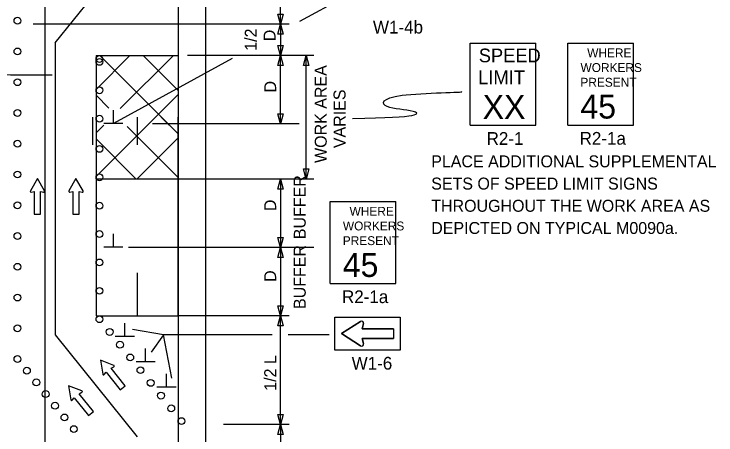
# Model space of a CAD drawing. Extents: x 16525 to 18479, y 5726 to 6926.
# Drawn here: x 16973 to 17383.9, y 6323.4 to 6569.7 of the extents above; entities that cross this region are included whole.
import ezdxf

# ---------------------------------------------------------------- set-up
doc = ezdxf.new("R2010")
doc.units = 0
for name, color, linetype in [('ALI_LEGAL_EX', 7, 'Continuous'), ('MT_SCRATCH_LEVEL_A', 7, 'Continuous'), ('MT_SCRATCH_LEVEL_E', 7, 'Continuous'), ('PAVT_EDGE_EX', 7, 'Continuous'), ('TRAFFIC_SIGNS_PR', 7, 'Continuous'), ('TYPICAL_TEXT_DIMEN_PR', 7, 'Continuous')]:
    doc.layers.add(name, color=color, linetype=linetype)

msp = doc.modelspace()

# ---------------------------------------------------------------- linework, layer by layer
at = {"layer": 'ALI_LEGAL_EX'}
for points in [[(17019, 6509.42), (17019, 6493.24)], [(17019, 6509.42), (17019, 6493.24)], [(17045, 6509.42), (17045, 6493.24)], [(17045, 6509.42), (17045, 6493.24)], [(17045, 6418.24), (17045, 6393.24)]]:
    msp.add_lwpolyline(points, dxfattribs=at)
at = {"layer": 'MT_SCRATCH_LEVEL_A'}
for p, q in [((17021, 6545.42), (17069, 6545.42)), ((17021, 6525.61), (17040.8, 6545.42)), ((17069, 6499.61), (17023.19, 6545.42)), ((17035.2, 6514.35), (17066.26, 6545.42)), ((17069, 6525.07), (17048.65, 6545.42)), ((17021, 6474.7), (17069, 6522.7)), ((17028.49, 6514.66), (17021, 6522.16)), ((17069, 6499.61), (17059.19, 6509.42)), ((17069, 6509.42), (17069, 6393.18)), ((17069, 6425.24), (17069, 6509.42)), ((17069, 6509.42), (17069, 6393.18)), ((17069, 6425.24), (17069, 6509.42)), ((17021, 6500.15), (17025.63, 6504.78)), ((17021, 6500.15), (17025.63, 6504.78)), ((17069, 6474.16), (17039.24, 6503.91)), ((17069, 6474.16), (17039.38, 6503.77)), ((17044.55, 6473.15), (17021, 6496.7)), ((17044.9, 6473.15), (17069, 6497.24))]:
    msp.add_line(p, q, dxfattribs=at)
at = {"layer": 'MT_SCRATCH_LEVEL_E'}
for p, q in [((16986.68, 6473.41), (16982.57, 6466.17)), ((16986.68, 6473.41), (16982.57, 6466.17)), ((16986.68, 6473.41), (16982.57, 6466.17)), ((16986.68, 6473.41), (16982.57, 6466.17)), ((16990.83, 6466.17), (16986.68, 6473.41)), ((16990.83, 6466.17), (16986.68, 6473.41)), ((16990.83, 6466.17), (16986.68, 6473.41)), ((16990.83, 6466.17), (16986.68, 6473.41)), ((17009.26, 6473.41), (17005.15, 6466.17)), ((17009.26, 6473.41), (17005.15, 6466.17)), ((17013.41, 6466.17), (17009.26, 6473.41)), ((17013.41, 6466.17), (17009.26, 6473.41)), ((16983.05, 6465.48), (16984.83, 6465.8)), ((16983.05, 6465.48), (16984.83, 6465.8)), ((16983.05, 6465.48), (16984.83, 6465.8)), ((16983.05, 6465.48), (16984.83, 6465.8)), ((16984.83, 6465.8), (16984.83, 6452.54)), ((16984.83, 6465.8), (16984.83, 6452.54)), ((16984.83, 6465.8), (16984.83, 6452.54)), ((16984.83, 6465.8), (16984.83, 6452.54)), ((16988.57, 6452.54), (16988.57, 6465.8)), ((16988.57, 6465.8), (16990.35, 6465.48)), ((16988.57, 6452.54), (16988.57, 6465.8)), ((16988.57, 6465.8), (16990.35, 6465.48)), ((16988.57, 6452.54), (16988.57, 6465.8)), ((16988.57, 6465.8), (16990.35, 6465.48)), ((16988.57, 6452.54), (16988.57, 6465.8)), ((16988.57, 6465.8), (16990.35, 6465.48)), ((17005.63, 6465.48), (17007.41, 6465.8)), ((17005.63, 6465.48), (17007.41, 6465.8)), ((17007.41, 6465.8), (17007.41, 6452.54)), ((17007.41, 6465.8), (17007.41, 6452.54)), ((17011.15, 6452.54), (17011.15, 6465.8)), ((17011.15, 6465.8), (17012.93, 6465.48)), ((17011.15, 6452.54), (17011.15, 6465.8)), ((17011.15, 6465.8), (17012.93, 6465.48)), ((16984.83, 6452.54), (16988.57, 6452.54)), ((16984.83, 6452.54), (16988.57, 6452.54)), ((16984.83, 6452.54), (16988.57, 6452.54)), ((16984.83, 6452.54), (16988.57, 6452.54)), ((17007.41, 6452.54), (17011.15, 6452.54)), ((17007.41, 6452.54), (17011.15, 6452.54)), ((17023.57, 6367.17), (17024.91, 6358.95)), ((17031.34, 6364.13), (17023.57, 6367.17)), ((17023.57, 6367.17), (17024.91, 6358.95)), ((17031.34, 6364.13), (17023.57, 6367.17)), ((17025.71, 6358.72), (17026.9, 6360.08)), ((17025.71, 6358.72), (17026.9, 6360.08)), ((17026.9, 6360.08), (17035.21, 6349.76)), ((17026.9, 6360.08), (17035.21, 6349.76)), ((17029.81, 6362.43), (17031.4, 6363.3)), ((17029.81, 6362.43), (17031.4, 6363.3)), ((17038.13, 6352.1), (17029.81, 6362.43)), ((17038.13, 6352.1), (17029.81, 6362.43)), ((17004.93, 6352.25), (17006.27, 6344.03)), ((17012.7, 6349.21), (17004.93, 6352.25)), ((17004.93, 6352.25), (17006.27, 6344.03)), ((17012.7, 6349.21), (17004.93, 6352.25)), ((17035.21, 6349.76), (17038.13, 6352.1)), ((17035.21, 6349.76), (17038.13, 6352.1)), ((17011.17, 6347.51), (17012.76, 6348.38)), ((17011.17, 6347.51), (17012.76, 6348.38)), ((17007.07, 6343.8), (17008.26, 6345.16)), ((17007.07, 6343.8), (17008.26, 6345.16)), ((17008.26, 6345.16), (17016.58, 6334.83)), ((17008.26, 6345.16), (17016.58, 6334.83)), ((17019.49, 6337.18), (17011.17, 6347.51)), ((17019.49, 6337.18), (17011.17, 6347.51)), ((17016.58, 6334.83), (17019.49, 6337.18)), ((17016.58, 6334.83), (17019.49, 6337.18))]:
    msp.add_line(p, q, dxfattribs=at)
for centre, start, end in [((16982.98, 6465.94), 150.4248, 279.9638), ((16982.98, 6465.94), 150.4248, 279.9638), ((16982.98, 6465.94), 150.4248, 279.9638), ((16982.98, 6465.94), 150.4248, 279.9638), ((16990.42, 6465.94), 260.0362, 29.7731), ((16990.42, 6465.94), 260.0362, 29.7731), ((16990.42, 6465.94), 260.0362, 29.7731), ((16990.42, 6465.94), 260.0362, 29.7731), ((17005.56, 6465.94), 150.4248, 279.9638), ((17005.56, 6465.94), 150.4248, 279.9638), ((17013, 6465.94), 260.0362, 29.7731), ((17013, 6465.94), 260.0362, 29.7731), ((17031.16, 6363.7), 298.877, 68.6139), ((17031.16, 6363.7), 298.877, 68.6139), ((17025.37, 6359.03), 189.2656, 318.8046), ((17025.37, 6359.03), 189.2656, 318.8046), ((17012.52, 6348.78), 298.877, 68.6139), ((17012.52, 6348.78), 298.877, 68.6139), ((17006.73, 6344.11), 189.2656, 318.8046), ((17006.73, 6344.11), 189.2656, 318.8046)]:
    msp.add_arc(centre, 0.463, start, end, dxfattribs=at)
at = {"layer": 'PAVT_EDGE_EX'}
for p, q in [((17069, 6926.09), (17069, 6062.8)), ((17085, 6926.09), (17085, 6062.8)), ((16991.07, 6912.1), (16991.07, 6082.91)), ((16997, 6552.78), (17045, 6612.39)), ((16997, 6552.78), (16997, 6381.96)), ((17021, 6545.42), (17021, 6393.18)), ((16997, 6381.96), (17045, 6322.35))]:
    msp.add_line(p, q, dxfattribs=at)
msp.add_lwpolyline([(17069, 6473.15), (17021.04, 6473.15), (17021.04, 6393.18), (17069, 6393.18)], close=True, dxfattribs=at)
at = {"layer": 'TRAFFIC_SIGNS_PR'}
for p, q in [((17239.99, 6552.62), (17278.39, 6552.62)), ((17239.99, 6504.62), (17239.99, 6552.62)), ((17278.39, 6504.62), (17278.39, 6552.62)), ((17297.18, 6552.71), (17335.58, 6552.71)), ((17297.18, 6504.71), (17297.18, 6552.71)), ((17335.58, 6504.71), (17335.58, 6552.71)), ((17239.99, 6504.62), (17278.39, 6504.62)), ((17297.18, 6504.71), (17335.58, 6504.71)), ((17158.1, 6460.01), (17196.5, 6460.01)), ((17158.1, 6412.01), (17158.1, 6460.01)), ((17196.5, 6412.01), (17196.5, 6460.01)), ((17158.1, 6412.01), (17196.5, 6412.01)), ((17175.84, 6389.81), (17164.68, 6382.7)), ((17176.69, 6385.5), (17177.52, 6388.56)), ((17195.08, 6385.5), (17176.69, 6385.5)), ((17195.08, 6385.5), (17195.08, 6379.9)), ((17164.68, 6382.7), (17175.84, 6375.6)), ((17177.52, 6376.84), (17176.69, 6379.9)), ((17176.69, 6379.9), (17195.08, 6379.9))]:
    msp.add_line(p, q, dxfattribs=at)
msp.add_lwpolyline([(17199.08, 6373.1), (17160.68, 6373.1), (17160.68, 6392.3), (17199.08, 6392.3)], close=True, dxfattribs=at)
for points in [[(17175.84, 6375.6), (17164.68, 6382.7), (17175.84, 6389.81)], [(17177.52, 6388.56), (17176.69, 6385.5), (17195.08, 6385.5), (17195.08, 6379.9), (17176.69, 6379.9), (17177.52, 6376.84)]]:
    msp.add_lwpolyline(points, dxfattribs=at)
for centre in [(16975, 6565.82), (16975, 6547.82), (17023, 6543.41), (17023, 6541.72), (16975, 6529.82), (17023, 6525.1), (16975, 6511.82), (17023, 6508.49), (16975, 6493.82), (17023, 6490.8), (16975, 6475.82), (17023, 6474.19), (16975, 6457.82), (17023, 6457.58), (17023, 6440.97), (16975, 6439.82), (17023, 6424.36), (16975, 6421.82), (17023, 6407.74), (16975, 6403.82), (17023, 6391.13), (16975, 6385.82), (17029, 6383.68), (17035, 6376.23), (16975, 6367.82), (17041, 6368.78), (16980.5, 6360.99), (17047, 6361.32), (16986, 6354.16), (17053, 6353.87), (16991.5, 6347.33), (17059, 6346.42), (16997, 6340.5), (17065, 6338.97), (17002.5, 6333.67), (17071, 6331.52), (17008, 6326.84)]:
    msp.add_circle(centre, 2, dxfattribs=at)
for centre, start, end in [((17176.44, 6388.86), 344.6731, 122.4696), ((17176.44, 6388.86), 344.6731, 122.4696), ((17176.44, 6376.55), 237.5304, 15.3269), ((17176.44, 6376.55), 237.5304, 15.3269)]:
    msp.add_arc(centre, 1.12, start, end, dxfattribs=at)
at = {"layer": 'TYPICAL_TEXT_DIMEN_PR'}
for p, q in [((17129, 6563.82), (17129, 6622.47)), ((17176.23, 6585.1), (17140.02, 6565.3)), ((17129, 6563.82), (17127.43, 6569.69)), ((17127.43, 6569.69), (17129, 6569.69)), ((17129, 6569.69), (17130.57, 6569.69)), ((17130.57, 6569.69), (17129, 6563.82)), ((17134, 6563.82), (16984.16, 6563.82)), ((17127.43, 6557.96), (17129, 6563.82)), ((17129, 6563.82), (17130.57, 6557.96)), ((17129, 6563.82), (17129, 6545.42)), ((17129, 6557.96), (17127.43, 6557.96)), ((17130.57, 6557.96), (17129, 6557.96)), ((17129, 6545.42), (17127.43, 6551.28)), ((17127.43, 6551.28), (17129, 6551.28)), ((17129, 6551.28), (17130.57, 6551.28)), ((17130.57, 6551.28), (17129, 6545.42)), ((17148.57, 6545.42), (17074.5, 6545.42)), ((17127.43, 6539.55), (17129, 6545.42)), ((17129, 6505.42), (17129, 6545.42)), ((17129, 6545.42), (17130.57, 6539.55)), ((17142.43, 6539.55), (17144, 6545.42)), ((17144, 6473.18), (17144, 6545.42)), ((17144, 6545.42), (17145.57, 6539.55)), ((17100.59, 6543.74), (17031.13, 6505.76)), ((17129, 6539.55), (17127.43, 6539.55)), ((17130.57, 6539.55), (17129, 6539.55)), ((17144, 6539.55), (17142.43, 6539.55)), ((17145.57, 6539.55), (17144, 6539.55)), ((17031.13, 6505.76), (17031.13, 6513.54)), ((17129, 6505.42), (17127.43, 6511.28)), ((17127.43, 6511.28), (17129, 6511.28)), ((17129, 6511.28), (17130.57, 6511.28)), ((17130.57, 6511.28), (17129, 6505.42)), ((17036.75, 6505.76), (17025.5, 6505.76)), ((17139.87, 6505.42), (17054.06, 6505.42)), ((17144, 6473.18), (17142.43, 6479.05)), ((17142.43, 6479.05), (17144, 6479.05)), ((17144, 6479.05), (17145.57, 6479.05)), ((17145.57, 6479.05), (17144, 6473.18)), ((17148.57, 6473.18), (17069, 6473.18)), ((17127.43, 6467.32), (17129, 6473.18)), ((17129, 6473.18), (17129, 6433.18)), ((17129, 6473.18), (17130.57, 6467.32)), ((17129, 6467.32), (17127.43, 6467.32)), ((17130.57, 6467.32), (17129, 6467.32)), ((17031.13, 6433.33), (17031.13, 6441.12)), ((17129, 6433.18), (17127.43, 6439.05)), ((17127.43, 6439.05), (17129, 6439.05)), ((17129, 6439.05), (17130.57, 6439.05)), ((17130.57, 6439.05), (17129, 6433.18)), ((17036.75, 6433.33), (17025.5, 6433.33)), ((17148.57, 6433.18), (17039.94, 6433.18)), ((17127.43, 6427.32), (17129, 6433.18)), ((17129, 6433.18), (17129, 6393.18)), ((17129, 6433.18), (17130.57, 6427.32)), ((17129, 6427.32), (17127.43, 6427.32)), ((17130.57, 6427.32), (17129, 6427.32)), ((17129, 6393.18), (17127.43, 6399.05)), ((17127.43, 6399.05), (17129, 6399.05)), ((17129, 6399.05), (17130.57, 6399.05)), ((17130.57, 6399.05), (17129, 6393.18)), ((17134, 6393.18), (17069, 6393.18)), ((17127.43, 6387.32), (17129, 6393.18)), ((17129, 6393.18), (17130.57, 6387.32)), ((17129, 6329.52), (17129, 6393.18)), ((17037.82, 6381.1), (17037.82, 6388.88)), ((17060.4, 6381.92), (17042.4, 6385.18)), ((17129, 6387.32), (17127.43, 6387.32)), ((17130.57, 6387.32), (17129, 6387.32)), ((17043.44, 6381.1), (17032.19, 6381.1)), ((17060.4, 6381.92), (17053.25, 6371.85)), ((17065.45, 6356.62), (17060.4, 6381.92)), ((17124.02, 6381.92), (17060.4, 6381.92)), ((17157.37, 6381.92), (17133.51, 6381.92)), ((17050.04, 6366.24), (17050.04, 6374.02)), ((17055.67, 6366.24), (17044.42, 6366.24)), ((17062.27, 6351.38), (17062.27, 6359.16)), ((17067.89, 6351.38), (17056.64, 6351.38)), ((17129, 6329.52), (17127.43, 6335.38)), ((17127.43, 6335.38), (17129, 6335.38)), ((17129, 6335.38), (17130.57, 6335.38)), ((17130.57, 6335.38), (17129, 6329.52)), ((17134, 6329.52), (17095.62, 6329.52)), ((17127.43, 6323.65), (17129, 6329.52)), ((17129, 6329.52), (17129, 6289.52)), ((17129, 6329.52), (17130.57, 6323.65)), ((17129, 6323.65), (17127.43, 6323.65)), ((17130.57, 6323.65), (17129, 6323.65))]:
    msp.add_line(p, q, dxfattribs=at)
for points, degree in [([(16995.27, 6533.91), (16910.49, 6533.91), (16910.49, 6541.79), (16946.45, 6541.79), (16946.45, 6547.94), (16898.15, 6547.94), (16894.21, 6547.94)], 2), ([(17171.02, 6508.68), (17212.26, 6509.15), (17209.66, 6513.9), (17187.7, 6513.9), (17187.7, 6523.8), (17237.35, 6523.8), (17234.86, 6524.35)], 3)]:
    msp.add_open_spline(points, degree=degree, dxfattribs=at)

# ---------------------------------------------------------------- texts
at = {"layer": 'TRAFFIC_SIGNS_PR'}
for s, height, p in [('W1-4b', 7.44, (17183.09, 6558.31)), ('SPEED', 8, (17245.02, 6541.48)), ('WHERE', 5.2, (17308.49, 6544.39)), ('WORKERS', 5.2, (17304.57, 6535.79)), ('LIMIT', 8, (17244.69, 6528.68)), ('PRESENT', 5.2, (17304.5, 6527.19)), ('XX', 14.031, (17247.29, 6508.38)), ('45', 14.031, (17304.49, 6508.56)), ('R2-1', 7.44, (17249.6, 6493.18)), ('R2-1a', 7.44, (17304.04, 6493.27)), ('PLACE ADDITIONAL SUPPLEMENTAL', 7, (17217.18, 6480.01)), ('SETS OF SPEED LIMIT SIGNS', 7, (17217.18, 6467.01)), ('THROUGHOUT THE WORK AREA AS', 7, (17217.18, 6454.01)), ('WHERE', 5.2, (17169.41, 6451.7)), ('WORKERS', 5.2, (17165.49, 6443.1)), ('DEPICTED ON TYPICAL M0090a.', 7, (17217.18, 6441.01)), ('PRESENT', 5.2, (17165.42, 6434.5)), ('45', 14.031, (17165.41, 6415.87)), ('R2-1a', 7.44, (17164.96, 6400.57)), ('W1-6', 7.44, (17170.62, 6361.66))]:
    msp.add_text(s, height=height, dxfattribs=at).set_placement(p)
at = {"layer": 'TYPICAL_TEXT_DIMEN_PR'}
for s, p in [('1/2', (17115.07, 6548.23)), ('D', (17126.07, 6553.8)), ('WORK AREA', (17156.02, 6482.58)), ('D', (17126.44, 6523.81)), ('VARIES', (17167.02, 6491.23)), ('BUFFER', (17143.73, 6437.98)), ('D', (17126.44, 6454.38)), ('BUFFER', (17143.73, 6397.12)), ('D', (17126.44, 6412.98)), ('1/2 L', (17126.44, 6349.29))]:
    msp.add_text(s, height=7, rotation=90, dxfattribs=at).set_placement(p)

doc.saveas('drawing.dxf')
